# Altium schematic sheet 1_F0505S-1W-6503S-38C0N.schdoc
size 289 x 200 mm; Name: default297x210; Symbol: default297x210; Device: default297x210; Date: 2025.07.04; Rev: V1.1; Size: "A4"; Id: /; File: F0505S-1W-6503S-38C0N; Sheet: /; @Page No: 1; @Page Count: 1; @Schematic Name: F0505S-1W-6503S-38C0N; @Project Name: 全桥隔离电源-F0505S-1W-6503S-38C0N; @Board Name: F0505S-1W-6503S-38C0N; @Update Date: 2025-06-24; @Create Time: 13:57:14; @Update Time: 17:29:28; @Page Name: F0505S-1W-6503S-38C0N; @Create Date: 2025-06-24
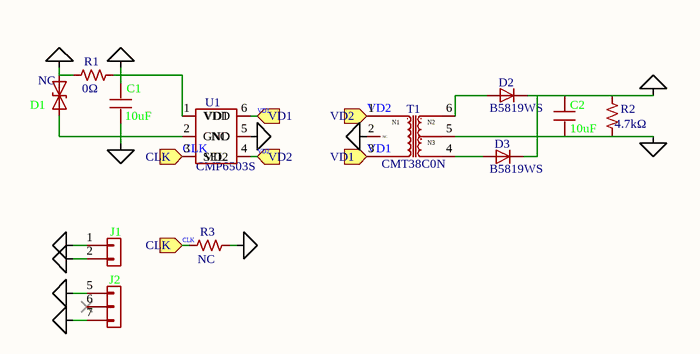
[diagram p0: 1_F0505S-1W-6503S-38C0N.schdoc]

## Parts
C1  10uF  [C0603]
C2  10uF  [C0603]
D1  NC  [SOD-123FL_L2.8-W1.8-LS3.7-BI]
D2  B5819WS  [SOD-323_L1.8-W1.3-LS2.5-RD]
D3  B5819WS  [SOD-323_L1.8-W1.3-LS2.5-RD]
J1  Connector_Generic_Conn_01x04  [coileasy:PinHeader_01x02_P2.54mm_Vertical]  (value not drawn)
J2  Connector_Generic_Conn_01x04  [coileasy:PinHeader_01x03_1_P2.54mm_Vertical]  (value not drawn)
R1  0Ω  [R0603]
R2  4.7kΩ  [R0603]
R3  NC  [R0603]
T1  CMT38C0N  [coileasy:CMT38xxx]
U1  CMP6503S  [coileasy:SOT-23-6]

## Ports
CLK (in), VD1 (in), VD2 (in)

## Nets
0V: C2.1 J2.5 R2.2 T1.5
+VO: C2.2 D2.1 D3.1 J2.7 R2.1
GND: C1.1 D1.2 J1.2 R3.2 U1.2(GND)
VCC: C1.2 R1.2 T1.2 U1.1(VDD) U1.5(NC)
VIN: D1.1 J1.1 R1.1
CLK: R3.1 U1.3(SEL) ; port CLK
VD1: T1.3 U1.6(VD1) ; port VD1
VD2: T1.1 U1.4(VD2) ; port VD2
NetD2_2: D2.2 T1.6
NetD3_2: D3.2 T1.4

Not connected (* = marked no-connect by the designer): J2 6*

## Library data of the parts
C1 C2 = 0603X106K100NT: Manufacturer: FH(风华); Symbol: My_Library_C; Add into BOM: yes; Tolerance: ±10%; Voltage Rated: 10V; Temperature Coefficient: X5R
D1 = D: Add into BOM: yes; polarity: 双向; Type: TVS
D2 D3 = B5819WS_C64886: Manufacturer: MDD(辰达半导体); Symbol: My_Library_D; Add into BOM: yes; Diode Configuration: 独立式; Forward Voltage (Vf@If): 900mV@3A; Reverse Voltage (Vr): 40V; Rectified Current: 1A; Reverse Leakage Current (Ir): 1mA@40V
J1 = Connector_Generic_Conn_01x04: Symbol: Conn_01x04_1; ki_fp_filters: Connector*:*_1x??_*; Value: Conn_01x02; Add into BOM: yes
J2 = Connector_Generic_Conn_01x04: ki_fp_filters: Connector*:*_1x??_*; Value: Conn_01x03; Add into BOM: yes
R1 = RC0603FR-070RL: Manufacturer: YAGEO(国巨); Symbol: R; Add into BOM: yes; Tolerance: ±1%; Power(Watts): 100mW; Voltage-Supply(Max): 75V
R2 = RC0603FR-074K7L: Manufacturer: YAGEO(国巨); Symbol: R; Add into BOM: yes; Tolerance: ±1%; Power(Watts): 100mW; Overload Voltage (Max): 75V; Temperature Coefficient: ±100ppm/℃
R3 = R: Add into BOM: yes; Tolerance: ±1%; Power(Watts): 100mW; Overload Voltage (Max): 75V; Temperature Coefficient: ±100ppm/℃
T1 = MYLibrary _CMT38xxxx: Users: REF**; Add into BOM: yes
U1 = CMP6503S: Manufacturer: coileasy(线易); Symbol: Coileasy_SOT23-6; Add into BOM: yes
